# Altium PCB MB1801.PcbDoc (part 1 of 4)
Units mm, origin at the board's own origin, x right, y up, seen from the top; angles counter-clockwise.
Board outline 70.1 x 57.1 mm, 4 copper layers (Top Layer, Signal Layer 1, Signal Layer 2, Bottom Layer), stack 1.614 mm thick; 219 components, 166 nets, 1002 pads, 473 vias.
Unrouted connection lines stored in the file: 2.
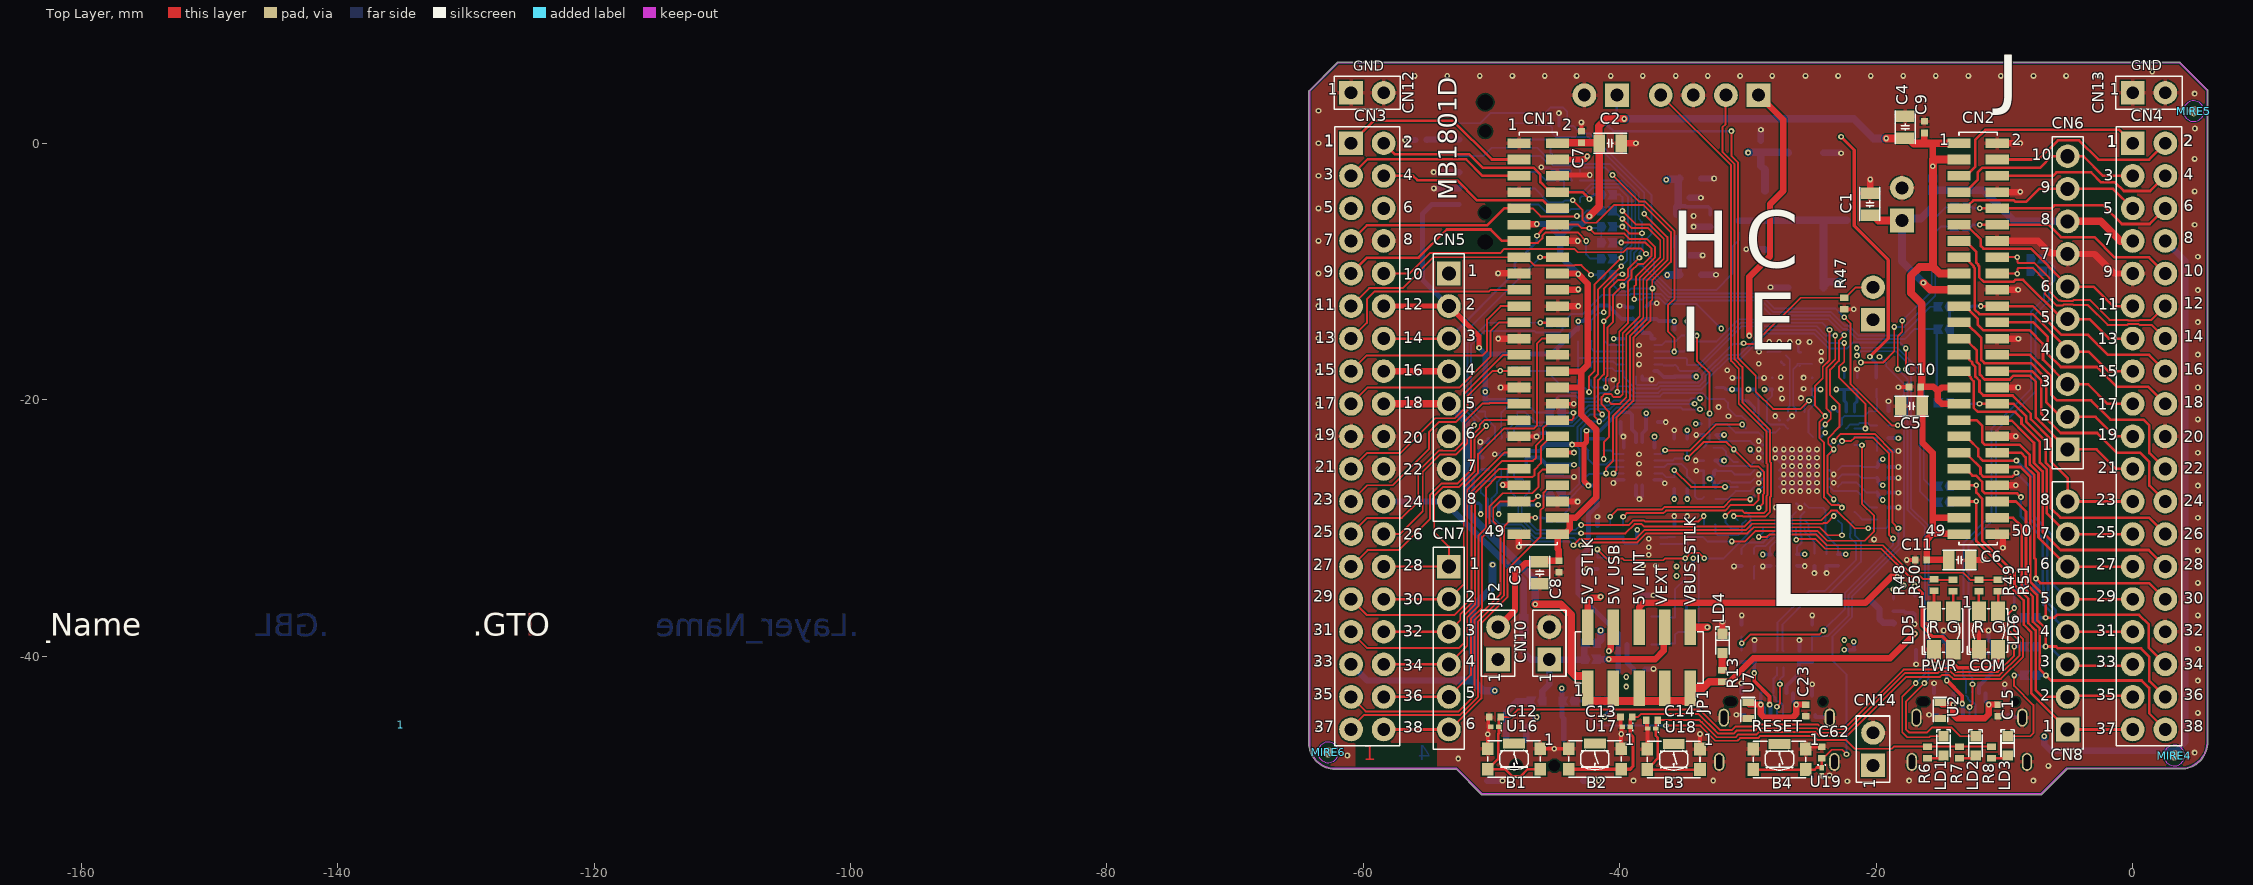
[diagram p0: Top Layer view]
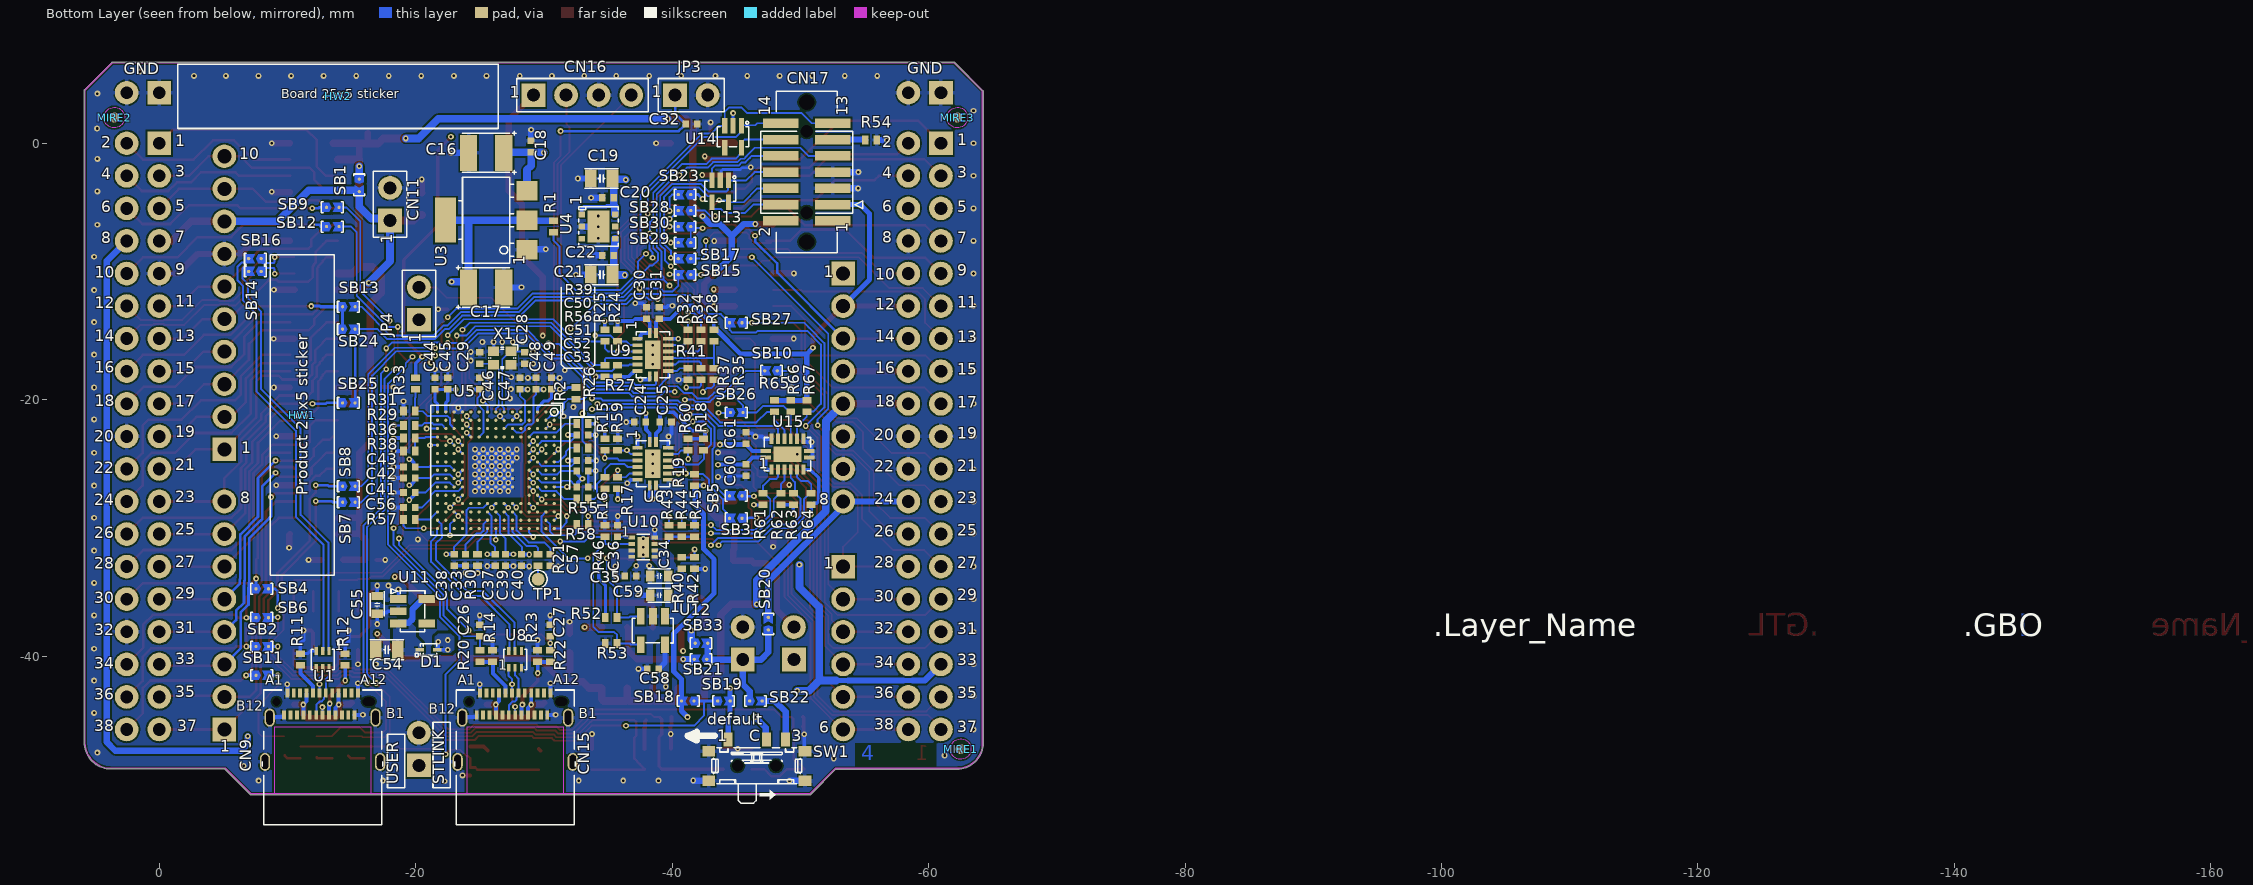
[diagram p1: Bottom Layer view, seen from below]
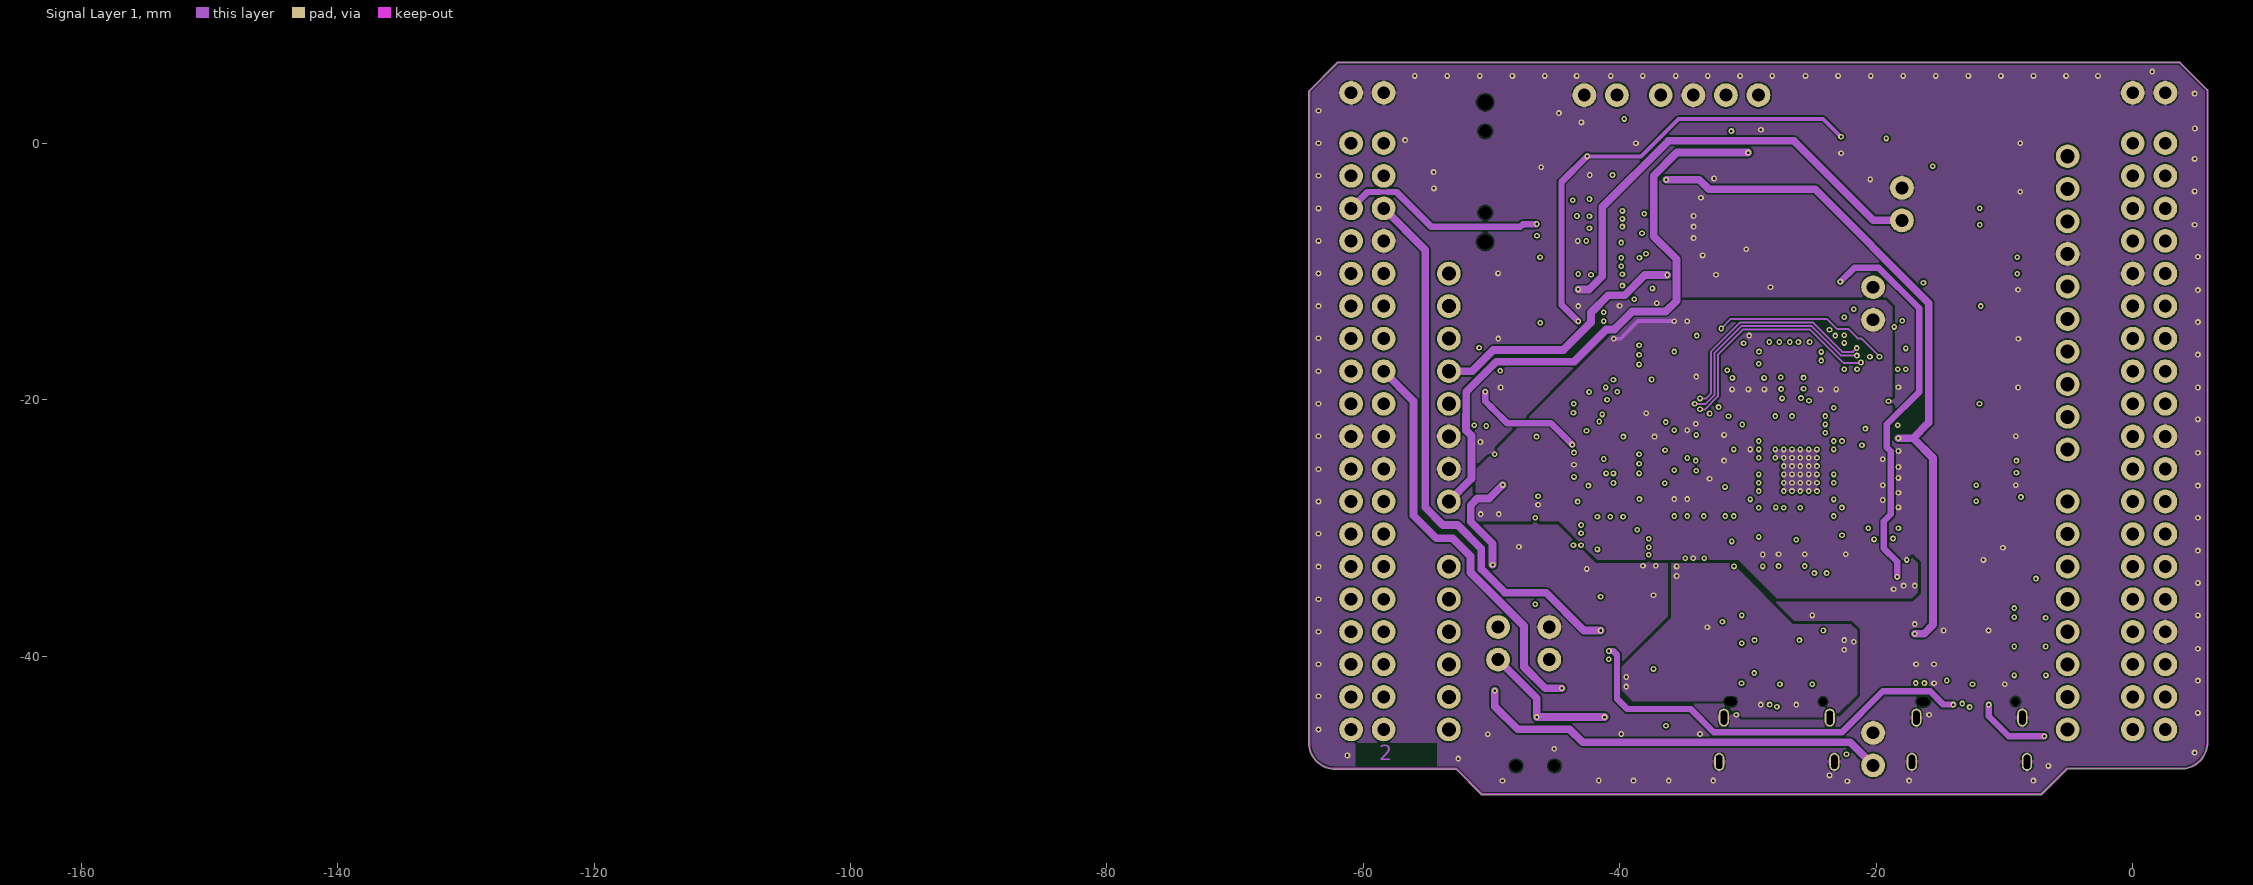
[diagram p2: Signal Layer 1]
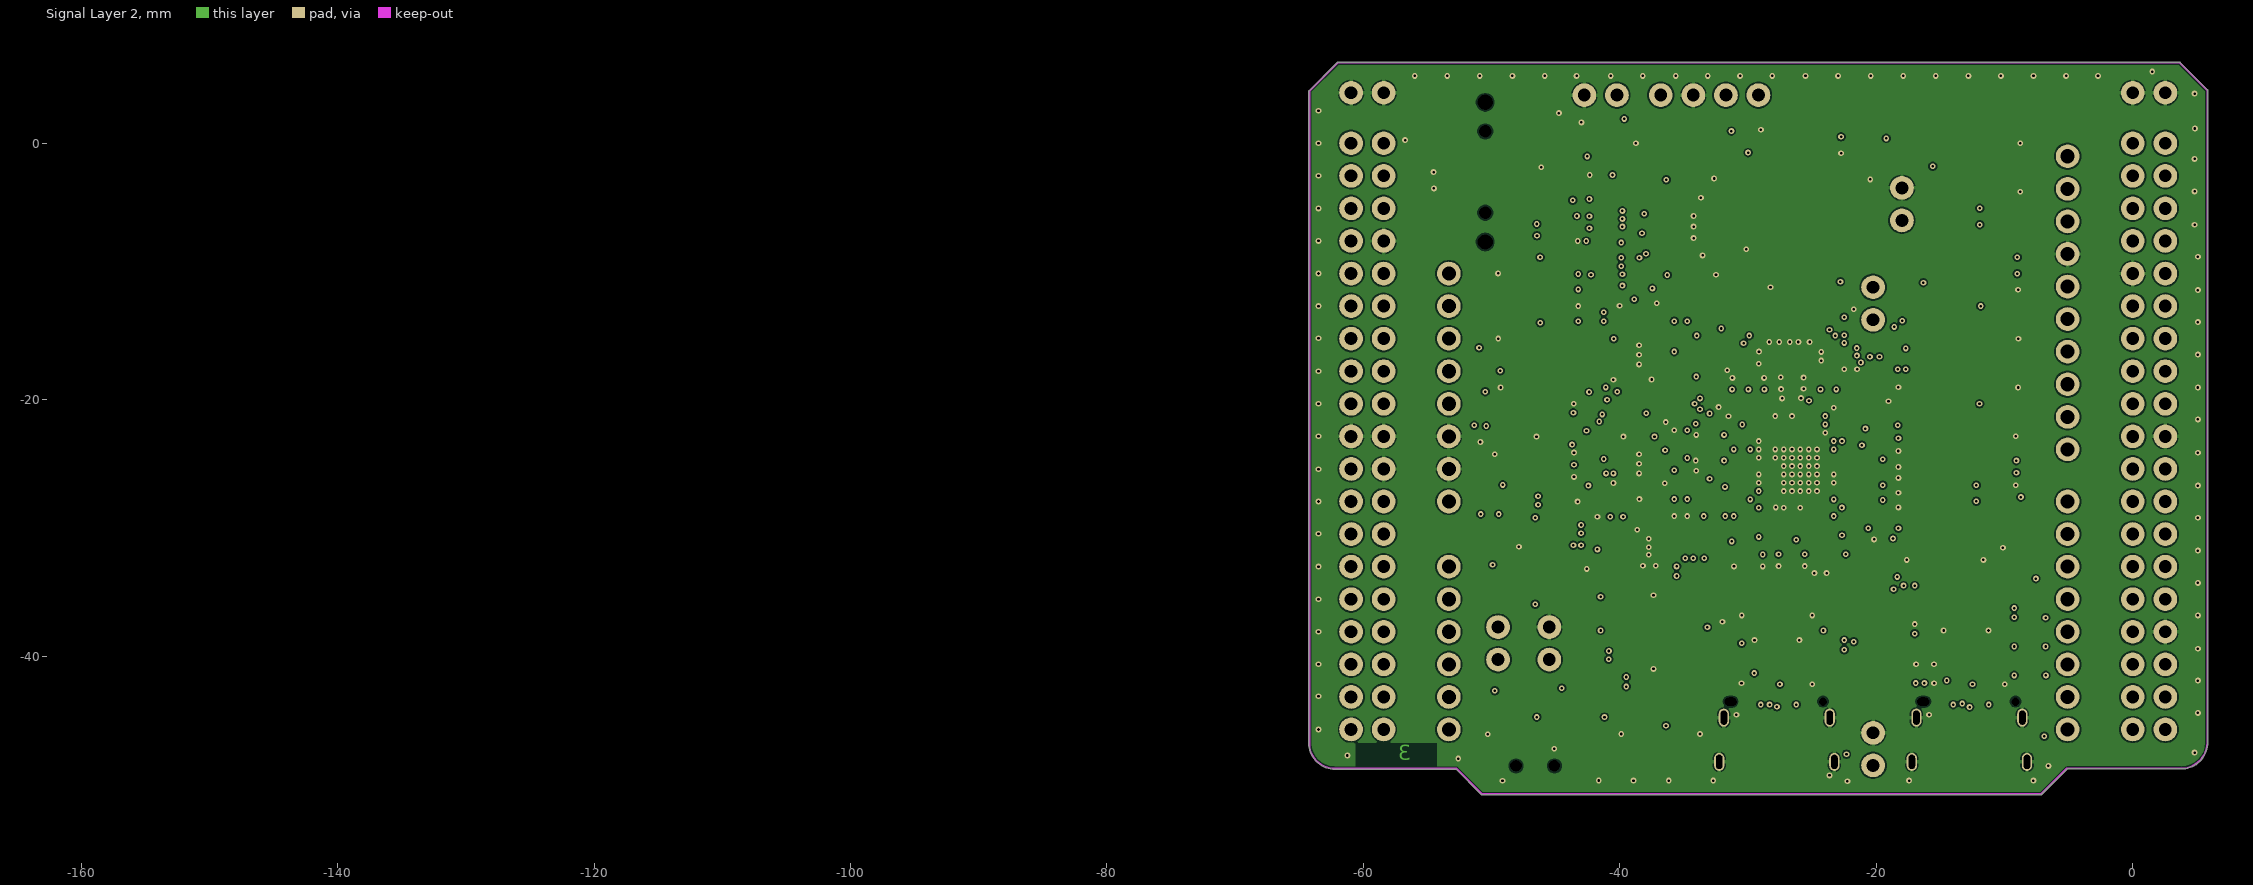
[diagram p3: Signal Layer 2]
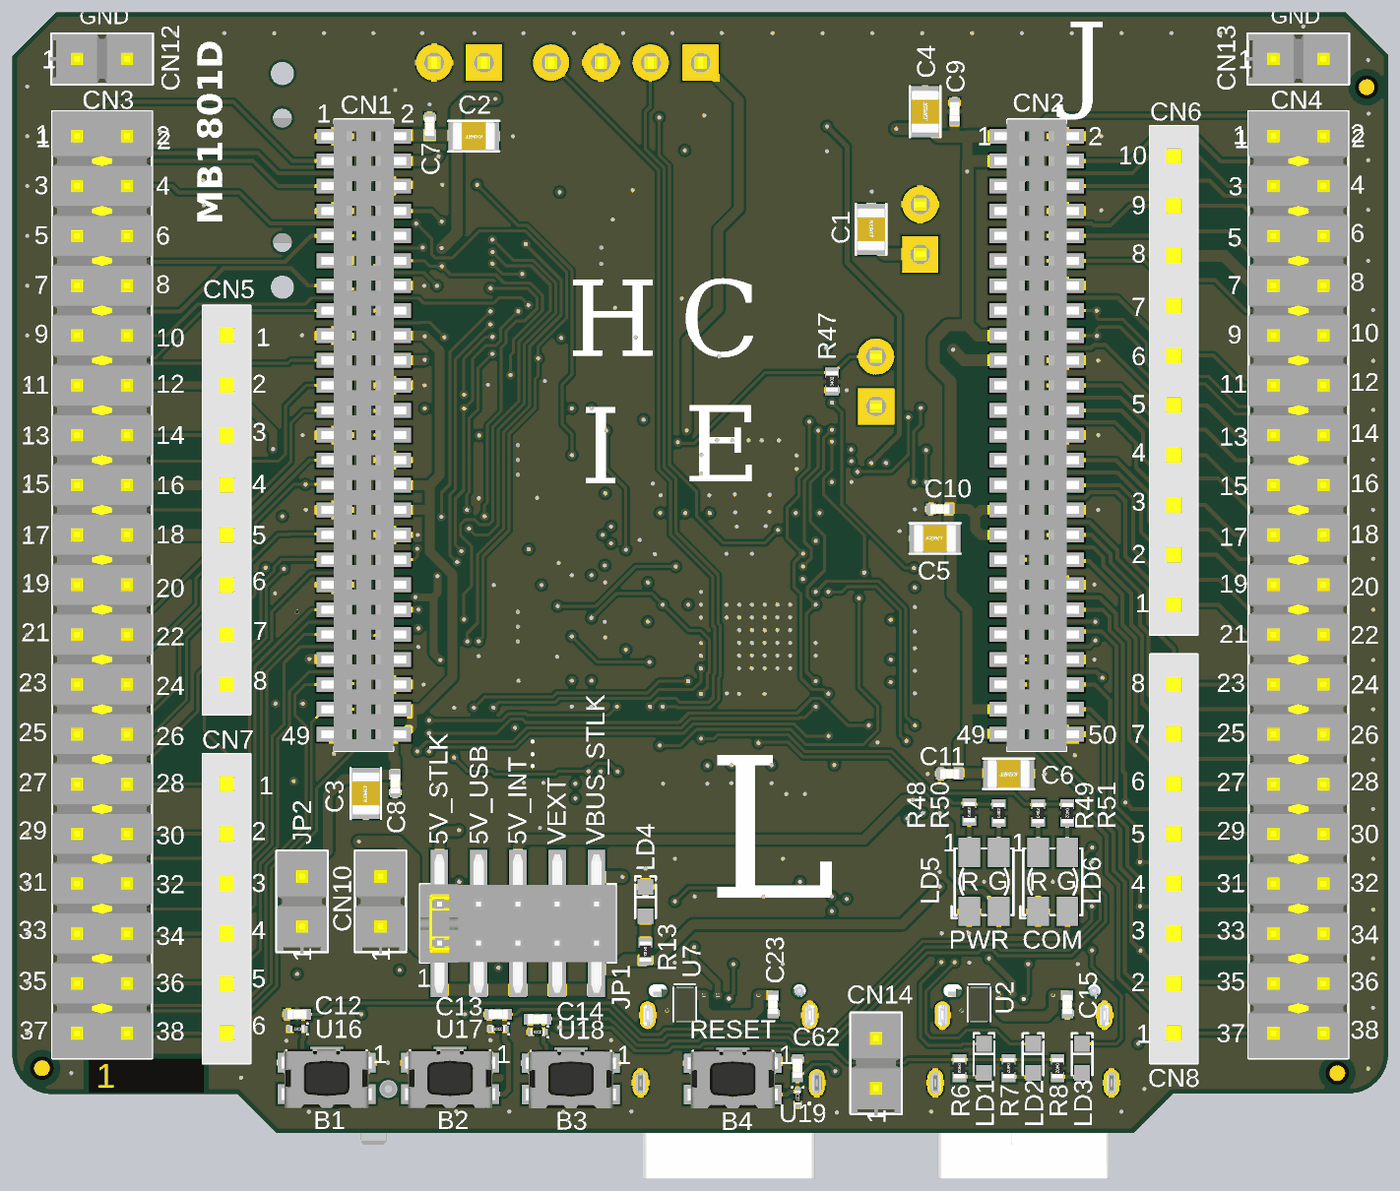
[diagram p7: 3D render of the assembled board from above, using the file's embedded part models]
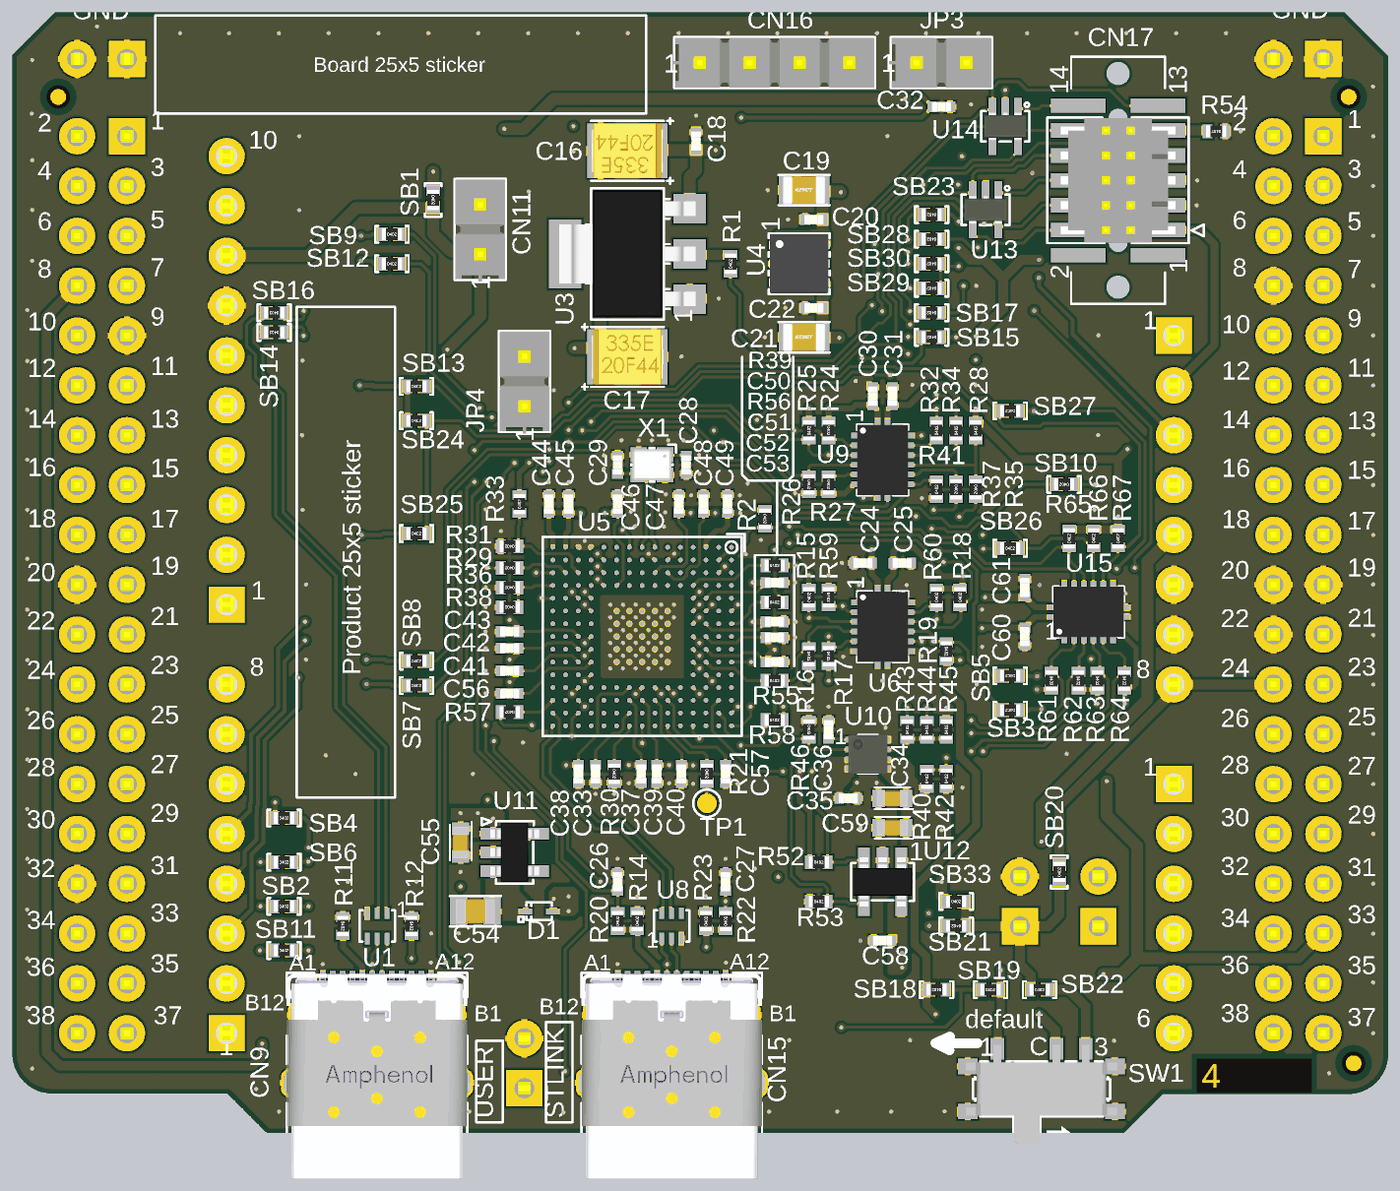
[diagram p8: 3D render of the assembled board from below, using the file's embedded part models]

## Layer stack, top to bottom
Top Solder: solder mask 0.015, Solder Resist, Dk 3.5
Top Layer: signal copper 0.042
Dielectric 1: prepreg 0.106, PP-IT-180A, Dk 4.2
Signal Layer 1: signal copper 0.035
Dielectric 2: dielectric 1.248, FR-4, Dk 4.2
Signal Layer 2: signal copper 0.035
Dielectric 3: prepreg 0.106, PP-IT-180A, Dk 4.2
Bottom Layer: signal copper 0.042
Bottom Solder: solder mask 0.015, Solder Resist, Dk 3.5

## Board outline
-62.21,-48.818 ccw(c-62.21,-48.768) -62.183,-48.81 -52.79,-48.81 -50.822,-50.778 ccw(c-50.786,-50.743) -50.786,-50.793 -7.131,-50.793 ccw(c-7.131,-50.743) -7.095,-50.778 -5.11,-48.793 3.79,-48.793 ccw(c3.79,-46.743) 5.84,-46.743 ccw(c5.79,-46.743) 5.84,-46.742 5.84,2.211 5.84,4.125 ccw(c5.79,4.125) 5.825,4.161 5.826,4.16 3.693,6.293 3.694,6.292 ccw(c3.658,6.257) 3.658,6.307 -62.001,6.307 ccw(c-62.001,6.257) -62.037,6.292 -62.037,6.293 -64.246,4.084 -64.245,4.084 ccw(c-64.21,4.048) -64.26,4.048 -64.26,-46.768 ccw(c-64.21,-46.768) -64.26,-46.769 cw(c-62.21,-46.768) -64.26,-46.768 -64.26,-46.769 ccw(c-62.21,-46.768)

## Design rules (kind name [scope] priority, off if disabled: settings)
Clearance [All] p1: gap=0.125 ignorepadtopadclearanceinfootprint=FALSE except(0.109: SMDPad-Via; 0.12: Arc-SMDPad Track-SMDPad; 0.223: Fill-Fill Fill-Poly Fill-Region Poly-Poly Poly-Region Region-Region)
ComponentClearance [All] p1: gap=0.2 collisioncheckmode=3 verticalgap=0.2 showdistances=FALSE
DiffPairsRouting [All] p1: maxlimit=0.226 minlimit=0.125 mostfreqgap=0.226 toplayer_minwidth=0.155 toplayer_maxwidth=0.155 toplayer_prefwidth=0.155 midlayer1_mingap=0.127 midlayer1_maxgap=0.127 midlayer1_prefgap=0.127 midlayer1_minwidth=0.083 midlayer1_maxwidth=0.083 midlayer1_prefwidth=0.083 midlayer2_mingap=0.127 midlayer2_maxgap=0.127 midlayer2_prefgap=0.127 midlayer2_minwidth=0.083 midlayer2_maxwidth=0.083 midlayer2_prefwidth=0.083 bottomlayer_mingap=0.15 bottomlayer_minwidth=0.155 bottomlayer_maxwidth=0.155 bottomlayer_prefwidth=0.155 impedanceprofiledriven=TRUE impedanceprofileid={D0817542-EEAA-4EE1-A293-D078BA0B5E8B} impedanceprofilevalue=90.000000 maxuncoupledlength=1.5
HoleSize [All] p1: absolutevalues=TRUE maxlimit=10 minlimit=0.025 maxpercent=80.000 minpercent=20.000
MatchedLengths "Schematic Matched Net Lengths_3" [InNet('USB_C_P')] p1: tolerance=2 checknetsindiffpair=TRUE checkdiffpairvsdiffpair=FALSE checkxsignals=FALSE checkothers=FALSE
MatchedLengths "Schematic Matched Net Lengths_2" [InNet('USB_C_N')] p2: tolerance=2 checknetsindiffpair=TRUE checkdiffpairvsdiffpair=FALSE checkxsignals=FALSE checkothers=FALSE
MatchedLengths "Schematic Matched Net Lengths_1" [InNet('USB_N')] p3: tolerance=2 checknetsindiffpair=TRUE checkdiffpairvsdiffpair=FALSE checkxsignals=FALSE checkothers=FALSE
MatchedLengths "Schematic Matched Net Lengths" [InNet('USB_P')] p4: tolerance=2 checknetsindiffpair=TRUE checkdiffpairvsdiffpair=FALSE checkxsignals=FALSE checkothers=FALSE
MaxMinImpedance "Schematic Impedance Constraint_4" [InNet('USB_FS_P')] p1: minimum=85.00 maximum=95.00
MaxMinImpedance "Schematic Impedance Constraint_3" [InNet('USB_FS_N')] p2: minimum=85.00 maximum=95.00
MaxMinImpedance "Schematic Impedance Constraint_2" [InNet('STLK_USB_P')] p3: minimum=85.00 maximum=95.00
MaxMinImpedance "Schematic Impedance Constraint_1" [InNet('STLK_USB_N')] p4: minimum=85.00 maximum=95.00
MaxMinImpedance "Schematic Impedance Constraint_8" [InNet('USB_C_N')] p5: minimum=85.00 maximum=95.00
MaxMinImpedance "Schematic Impedance Constraint_7" [InNet('USB_N')] p6: minimum=85.00 maximum=95.00
MaxMinImpedance "Schematic Impedance Constraint_6" [InNet('USB_C_P')] p7: minimum=85.00 maximum=95.00
MaxMinImpedance "Schematic Impedance Constraint" [InNet('USB_P')] p8: minimum=85.00 maximum=95.00
MinimumSolderMaskSliver [All] p1: minsoldermaskwidth=0.1
PlaneConnect [All] p1: planeconnectstyle=Direct reliefexpansion=0.508 reliefentries=4 reliefconductorwidth=0.21 reliefairgap=0.21
PolygonConnect PolygonConnect_via [IsVia] p1: connectstyle=Direct reliefconductorwidth=0.254 reliefentries=4 polygonreliefangle="90 Angle" airgapwidth=0.254
PolygonConnect [All] p2: connectstyle=Relief reliefconductorwidth=0.3 reliefentries=4 polygonreliefangle="90 Angle" airgapwidth=0.1
RoutingVias [All] p1: holewidth=0.2 width=0.45 viastyle="Through Hole" minholewidth=0.2 minwidth=0.45 maxholewidth=0.2 maxwidth=0.45
SilkToSilkClearance [All] p1: silktosilkclearance=0.2
SilkToSolderMaskClearance [IsPad] p1: minsilkscreentomaskgap=0.2 clearancetoexposedcopper=TRUE
SolderMaskExpansion [All] p1: expansion=0.102 istentingtop=FALSE
Width [All] p1: maxlimit=0.8 minlimit=0.15 preferedwidth=0.15 minimp=50.000000 maximp=50.000000 favimp=50.000000
23 further rules are at their usual default settings.

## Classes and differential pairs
component class U_External_Debug_Interface: CN17 LD5 LD6 R48 R49 R50 R51 R54 U13 U14
component class Project_Overview: HW1 HW2
component class U_STlink-V3EC: C23 C24 C25 C26 C27 C28 C29 C30 C31 C32 C33 C34 C35 C36 C37 C38 C39 C40 C41 C42 C43 C44 C45 C46 C47 C48 C49 C50 C51 C52 C53 C54 C55 C56 C57 C58 C59 C60 C61 CN15 CN16 D1 JP3 JP4 R2 R14 R15 R16 R17 R18 R19 R20 R21 R22 R23 R24 R25 R26 R27 R28 R29 R30 R31 R32 R33 R34 R35 R36 R37 R38 R39 R40 R41 R42 R43 R44 R45 R46 R47 R52 R53 R55 R56 R57 R58 R59 R60 R61 R62 R63 R64 R65 R66 R67 TP1 U5 U6 U7 U8 U9 U10 U11 U12 U15 X1
component class "Power Management": C16 C17 C18 C19 C20 C21 C22 CN10 CN12 CN13 JP1 JP2 LD4 R13 SB20 SB21 SB22 SB33 SW1 U3 U4
component class "LEDs & Push Buttons & USB-C Connector": B1 B2 B3 B4 C12 C13 C14 C15 C62 CN9 LD1 LD2 LD3 R6 R7 R8 R11 R12 SB18 SB19 U1 U2 U16 U17 U18 U19
component class "Extension Connectors": C1 C2 C3 C4 C5 C6 C7 C8 C9 C10 C11 CN1 CN2 CN3 CN4 CN5 CN6 CN7 CN8 CN11 CN14 R1 SB1 SB2 SB3 SB4 SB5 SB6 SB7 SB8 SB9 SB10 SB11 SB12 SB13 SB14 SB15 SB16 SB17 SB23 SB24 SB25 SB26 SB27 SB28 SB29 SB30
differential pair USB_FS: +USB_FS_P -USB_FS_N
differential pair STLK_USB: +STLK_USB_P -STLK_USB_N
differential pair USB: +USB_P -USB_N
differential pair USB_C: +USB_C_P -USB_C_N

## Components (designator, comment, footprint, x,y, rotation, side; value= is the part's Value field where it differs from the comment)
1 "Comment" Sheetbox_2L2S -180.167,-50.702 r0 top
B1 "SW-PUSH-CMS_KMR2_BLACK" SWI_C&K_Y78B23110FP__ITT_KMR231GLFS -48.25,-48.022 r0 top value=KMR231GLFS
B2 "SW-PUSH-CMS_KMR2_BLACK" SWI_C&K_Y78B23110FP__ITT_KMR231GLFS -41.95,-48.022 r0 top value=KMR231GLFS
B3 "SW-PUSH-CMS_KMR2_BLACK" SWI_C&K_Y78B23110FP__ITT_KMR231GLFS -35.8,-48.05 r0 top value=KMR231GLFS
B4 "SW-PUSH-CMS_KMR2_BLACK" SWI_C&K_Y78B23110FP__ITT_KMR231GLFS -27.55,-48.05 r0 top value=KMR231GLFS
C1 "Capacitor" C0805_H0P85 -20.5,-4.75 r270 top value=1uF
C2 "Capacitor" C0805_H0P85 -40.75,0 r180 top value=1uF
C3 "Capacitor" C0805_H0P85 -46.25,-33.5 r90 top value=1uF
C4 "Capacitor" C0805_H0P85 -17.75,1.25 r270 top value=1uF
C5 "Capacitor" C0805_H0P85 -17.25,-20.5 r0 top value=1uF
C6 "Capacitor" C0805_H0P85 -13.5,-32.5 r180 top value=1uF
C7 "Capacitor" C0402 -43,0.5 r270 top value=100nF
C8 "Capacitor" C0402 -44.75,-33 r90 top value=100nF
C9 "Capacitor" C0402 -16.25,1.25 r270 top value=100nF
C10 "Capacitor" C0402 -17,-19 r0 top value=100nF
C11 "Capacitor" C0402 -16.5,-32.5 r0 top value=100nF
C12 "Capacitor" C0402 -49.75,-44.75 r0 top value=10nF
C13 "Capacitor" C0402 -39.5,-44.75 r0 top value=10nF
C14 "Capacitor" C0402 -37.5,-45 r0 top value=10nF
C15 "Capacitor" C0402 -10.5,-44.25 r90 top value=100pF
C16 "Cap_POL_TANA" CPOL_TAJ-B_1210_H210 -25.5,-0.75 r0 bottom value=10uF
C17 "Cap_POL_TANA" CPOL_TAJ-B_1210_H210 -25.5,-11.25 r180 bottom value=10uF
C18 "Capacitor" C0402 -29,-0.25 r270 bottom value=100nF
C19 "Capacitor" C0805_H0P85 -34.5,-2.75 r180 bottom value=1uF
C20 "Capacitor" C0402 -35,-4.25 r180 bottom value=100nF
C21 "Capacitor" C0805_H0P85 -34.5,-10.25 r180 bottom value=1uF
C22 "Capacitor" C0402 -35,-8.75 r180 bottom value=100nF
C23 "Capacitor" C0402 -25.5,-44.25 r270 top value=100pF
C24 "Capacitor" C0402 -37.5,-21.75 r180 bottom value=100nF
C25 "Capacitor" C0402 -39.5,-21.75 r180 bottom value=100nF
C26 "Capacitor" C0402 -25,-38 r90 bottom value=10nF
C27 "Capacitor" C0402 -30.5,-38 r90 bottom value=10nF
C28 "Capacitor" C0402 -28.5,-16.75 r90 bottom value=2.7pF
C29 "Capacitor" C0402 -25,-16.75 r90 bottom value=2.7pF
C30 "Capacitor" C0402 -38,-13.25 r270 bottom value=100nF
C31 "Capacitor" C0402 -39,-13.25 r90 bottom value=100nF
C32 "Capacitor" C0402 -41.5,1.5 r0 bottom value=100nF
C33 "Capacitor" C0402 -23.875,-32.5 r90 bottom value=2.2uF
C34 "Capacitor" C0603 -39,-33.75 r180 bottom value=10uF
C35 "Capacitor" C0402 -36.75,-33.75 r0 bottom value=100nF
C36 "Capacitor" C0402 -35.75,-30.25 r270 bottom value=10nF
C37 "Capacitor" C0402 -26.2,-32.5 r270 bottom value=100nF
C38 "Capacitor" C0402 -23,-32.5 r270 bottom value=100nF
C39 "Capacitor" C0402 -27,-32.5 r270 bottom value=100nF
C40 "Capacitor" C0402 -28.25,-32.5 r270 bottom value=100nF
C41 "Capacitor" C0402 -19.5,-27.25 r0 bottom value=100nF
C42 "Capacitor" C0402 -19.5,-26.1 r0 bottom value=100nF
C43 "Capacitor" C0402 -19.5,-25.25 r0 bottom value=100nF
C44 "Capacitor" C0402 -21.5,-18.75 r90 bottom value=100nF
C45 "Capacitor" C0402 -22.5,-18.75 r90 bottom value=100nF
C46 "Capacitor" C0402 -25,-18.75 r90 bottom value=100nF
C47 "Capacitor" C0402 -28.125,-18.75 r90 bottom value=100nF
C48 "Capacitor" C0402 -29.375,-18.75 r90 bottom value=100nF
C49 "Capacitor" C0402 -30.6,-18.75 r90 bottom value=100nF
C50 "Capacitor" C0402 -33,-22.75 r180 bottom value=100nF
C51 "Capacitor" C0402 -33,-24.75 r180 bottom value=100nF
C52 "Capacitor" C0402 -33,-25.55 r180 bottom value=100nF
C53 "Capacitor" C0402 -33,-26.8 r180 bottom value=100nF
C54 "Capacitor" C0805 -17.75,-39.5 r180 bottom value=2.2uF
C55 "Capacitor" C0603 -17,-36 r90 bottom value=10uF
C56 "Capacitor" C0402 -19.5,-28.4 r180 bottom value=2.2uF
C57 "Capacitor" C0402 -30.5,-32.5 r90 bottom value=2.2uF
C58 "Capacitor" C0402 -38.5,-41 r180 bottom value=100nF
C59 "Capacitor" C0603 -39,-35.25 r180 bottom value=10uF
C60 "Capacitor" C0402 -45.75,-25.5 r90 bottom value=100nF
C61 "Capacitor" C0402 -45.75,-23 r90 bottom value=100nF
C62 "Capacitor" C0402 -24.25,-47.5 r90 top value=100nF
CN1 "CLP-125-02-F-D" CON_SAMTEC_CLP-125-02-F-D -46.355,-15.24 r0 top locked value="Socket 25x2"
CN2 "CLP-125-02-F-D" CON_SAMTEC_CLP-125-02-F-D -12.065,-15.24 r0 top locked value="Socket 25x2"
CN3 "Header 19x2" CON_SAMTEC_TSW-119-09-X-D -59.69,-22.86 r270 top locked
CN4 "Header 19x2" CON_SAMTEC_TSW-119-09-X-D 1.27,-22.86 r270 top locked
CN5 "Socket 8x1" CON_SAMTEC_SSW-108-01-X-S -53.34,-19.05 r270 top locked
CN6 "Socket 10x1" CON_SAMTEC_SSW-110-01-X-S -5.08,-12.446 r90 top locked
CN7 "Socket 6x1" CON_SAMTEC_SSW-106-01-X-S -53.34,-39.37 r270 top locked
CN8 "Socket 8x1" CON_SAMTEC_SSW-108-01-X-S -5.08,-36.83 r90 top locked
CN9 "USB_TYPE_C_Receptacle" CON_USB-TYPEC_AMPHENOL_12401826E412A -12.74,-43.55 r180 bottom value=USB_C_12401826E412A
CN10 "Header 2x1" CON_SAMTEC_TSW-102-07-G-S -45.5,-39 r90 top
CN11 "Header 2x1" CON_SAMTEC_TSW-102-07-G-S -18,-4.75 r90 bottom
CN12 "Header 2x1" CON_SAMTEC_TSW-102-07-G-S -59.69,3.937 r0 top
CN13 "Header 2x1" CON_SAMTEC_TSW-102-07-G-S 1.27,3.937 r0 top locked
CN14 "Header 2x1" CON_SAMTEC_TSW-102-07-G-S -20.25,-47.25 r90 top
CN15 "USB_TYPE_C_Receptacle" CON_USB-TYPEC_AMPHENOL_12401826E412A -27.76,-43.55 r180 bottom value=USB_C_12401826E412A
CN16 "Header 4x1" CON_SAMTEC_TSW-104-07-G-S -33,3.75 r180 bottom
CN17 "Header 7x2" CON_STDC14_Receiver_MEDIUM_WITH_MIPI10_3D -50.5,-2.25 r90 bottom value="Header 5x2"
D1 "SCHOTTKY_1A_2K" DIO_SOD523_1A_2K -21,-39.5 r0 bottom value=BAT54KFILM
HW1 "STICKER_PRODUCT" STICKER_PRODUCT_25X5 -11.15,-21.2 r270 bottom value="Sticker product"
HW2 "STICKER_BOARD" STICKER_BOARD_25X5 -13.95,3.65 r180 bottom value="Sticker board"
JP1 "Jumper 5 Positions" CON_SAMTEC_TMM-105-06-T-D-SM -38.5,-40.125 r0 top value=TMM-105-06-T-D-SM
JP2 "Jumper_Header 2x1 Fitted" CON_SAMTEC_TSW-102-07-G-S -49.5,-39 r90 top value="Header 2x1"
JP3 "Jumper_Header 2x1" CON_SAMTEC_TSW-102-07-G-S -41.5,3.75 r180 bottom
JP4 "Jumper_Header 2x1" CON_SAMTEC_TSW-102-07-G-S -20.25,-12.5 r90 bottom
LD1 "LED_blue" LED_0603_VISHAY_VLMB1300-GS08_BLUE_1A2K_H0P8 -14.75,-47 r90 top value=BLUE
LD2 "LED_green" LED_0603_VISHAY_VLMTG1300-GS08_GREEN_1A2K_H0P8 -12.25,-47 r90 top value="TRUE GREEN"
LD3 "LED_red" LED_0603_VISHAY_VLMS1300-GS08_RED_1A2K_H0P8 -9.75,-47 r90 top value=RED
LD4 "LED_green" LED_0603_VISHAY_VLMTG1300-GS08_GREEN_1A2K_H0P8 -32,-39 r90 top value="TRUE GREEN"
LD5 "LED_BICOLOR" LED_BI-GR_WE-150141SV73110 -14.75,-38 r0 top value="Green / Red"
LD6 "LED_BICOLOR" LED_BI-GR_WE-150141SV73110 -11.25,-38 r0 top value="Green / Red"
MIRE1 "Comment" MIRE_PLACE_SMD_0P8MM -62.5,-47.25 r0 bottom
MIRE2 "Comment" MIRE_PLACE_SMD_0P8MM 3.5,2 r0 bottom
MIRE3 "Comment" MIRE_PLACE_SMD_0P8MM -62.25,2 r0 bottom
MIRE4 "Comment" MIRE_PLACE_SMD_0P8MM 3.25,-47.75 r0 top
MIRE5 "Comment" MIRE_PLACE_SMD_0P8MM 4.75,2.5 r0 top
MIRE6 "Comment" MIRE_PLACE_SMD_0P8MM -62.75,-47.5 r0 top
R1 "Resistor" R0402 -30.75,-6.5 r90 bottom value=1K
R2 "Resistor" R0402 -32.5,-19.5 r270 bottom value=100K
R6 "Resistor" R0402 -16,-47.5 r270 top value=680R
R7 "Resistor" R0402 -13.5,-47.5 r270 top value=680R
R8 "Resistor" R0402 -11,-47.5 r270 top value=680R
R11 "Resistor" R0402 -11,-40.25 r270 bottom value=5K1
R12 "Resistor" R0402 -14.5,-40.25 r270 bottom value=5K1
R13 "Resistor" R0402 -32,-41.55 r270 top value=1K5
R14 "Resistor" R0402 -26,-40 r90 bottom value=5K1
R15 "Resistor" R0402 -34.75,-23.5 r90 bottom value=100K
R16 "Resistor" R0402 -34.75,-26.5 r270 bottom value=100K
R17 "Resistor" R0402 -35.75,-26.5 r270 bottom value=100K
R18 "Resistor" R0402 -42.45,-23.5 r90 bottom value=100K
R19 "Resistor" R0402 -41.75,-26.25 r270 bottom value=100K
R20 "Resistor" R0402 -25,-40 r90 bottom value=100K
R21 "Resistor" R0402 -29.55,-32.5 r270 bottom value=0R
R22 "Resistor" R0402 -30.5,-40 r90 bottom value=100K
R23 "Resistor" R0402 -29.5,-40 r90 bottom value=5K1
R24 "Resistor" R0402 -35.75,-15 r270 bottom value=100K
R25 "Resistor" R0402 -34.75,-15 r90 bottom value=100K
R26 "Resistor" R0402 -34.75,-17.75 r270 bottom value=100K
R27 "Resistor" R0402 -35.75,-17.75 r270 bottom value=100K
R28 "Resistor" R0402 -43.25,-15 r90 bottom value=100K
R29 "Resistor" R0402 -19.5,-22 r0 bottom value=0R
R30 "Resistor" R0402 -24.825,-32.5 r270 bottom value=3K
R31 "Resistor" R0402 -19.5,-20.9 r0 bottom value=10K
R32 "Resistor" R0402 -41.25,-15 r90 bottom value=47R
R33 "Resistor" R0402 -20,-18.75 r90 bottom value=10K
R34 "Resistor" R0402 -42.25,-15 r90 bottom value=47R
R35 "Resistor" R0402 -43.25,-18 r270 bottom value=47R
R36 "Resistor" R0402 -19.5,-23 r0 bottom value=5K1
R37 "Resistor" R0402 -42.25,-18 r270 bottom value=47R
R38 "Resistor" R0402 -19.5,-24 r0 bottom value=10K
R39 "Resistor" R0402 -33,-21.875 r180 bottom value=10K
R40 "Resistor" R0402 -40.75,-32.75 r90 bottom value=3K
R41 "Resistor" R0402 -41.25,-18 r90 bottom value=100K
R42 "Resistor" R0402 -41.75,-32.75 r90 bottom value=5K1
R43 "Resistor" R0402 -39.75,-30.25 r90 bottom value=1K8
R44 "Resistor" R0402 -40.75,-30.25 r90 bottom value=1K3
R45 "Resistor" R0402 -41.75,-30.25 r90 bottom value=3K9
R46 "Resistor" R0402 -34.75,-30.25 r270 bottom value=100K
R47 "Resistor" R0402 -22.5,-12.5 r90 top value=100K
R48 "Resistor" R0402 -15.5,-34.45 r90 top value=1K
R49 "Resistor" R0402 -12,-34.5 r90 top value=1K
R50 "Resistor" R0402 -14,-34.5 r90 top value=330R
R51 "Resistor" R0402 -10.5,-34.5 r270 top value=330R
R52 "Resistor" R0402 -35.25,-37 r180 bottom value=100K
R53 "Resistor" R0402 -35.25,-39 r180 bottom value=100K
R54 "Resistor" R0402 -55.5,0.25 r0 bottom value=100R
R55 "Resistor" R0402 -33,-27.75 r180 bottom value=0R
R56 "Resistor" R0402 -33,-23.75 r180 bottom value=33R
R57 "Resistor" R0402 -19.5,-29.35 r0 bottom value=0R
R58 "Resistor" R0402 -33,-29.75 r180 bottom value=33R
R59 "Resistor" R0402 -35.75,-23.5 r270 bottom value=100K
R60 "Resistor" R0402 -41.25,-23.5 r90 bottom value=100K
R61 "Resistor" R0402 -47.1,-27.75 r270 bottom value=100K
R62 "Resistor" R0402 -48.475,-27.75 r270 bottom value=100K
R63 "Resistor" R0402 -49.45,-27.75 r270 bottom value=100K
R64 "Resistor" R0402 -50.825,-27.75 r270 bottom value=100K
R65 "Resistor" R0402 -48,-20.5 r90 bottom value=100K
R66 "Resistor" R0402 -49.25,-20.5 r90 bottom value=100K
R67 "Resistor" R0402 -50.5,-20.5 r90 bottom value=100K
SB1 "SB_ON" SOLDER-BRIDGE_R0402-0R -15.6,-3.25 r270 bottom
SB2 "SB_ON" SOLDER-BRIDGE_R0402-0R -8,-39.25 r180 bottom
SB3 "SB_ON" SOLDER-BRIDGE_R0402-0R -45,-29.25 r0 bottom
SB4 "SB_ON" SOLDER-BRIDGE_R0402-0R -8,-34.75 r180 bottom
SB5 "SB_ON" SOLDER-BRIDGE_R0402-0R -45,-27.5 r0 bottom
SB6 "SB_ON" SOLDER-BRIDGE_R0402-0R -8,-37 r180 bottom
SB7 "SB_ON" SOLDER-BRIDGE_R0402-0R -14.75,-28 r180 bottom
SB8 "SB_ON" SOLDER-BRIDGE_R0402-0R -14.75,-26.75 r180 bottom
SB9 "SB_ON" SOLDER-BRIDGE_R0402-0R -13.5,-5 r180 bottom
SB10 "SB_ON" SOLDER-BRIDGE_R0402-0R -47.75,-17.75 r0 bottom
SB11 "SB_ON" SOLDER-BRIDGE_R0402-0R -8,-41.5 r180 bottom
SB12 "SB_ON" SOLDER-BRIDGE_R0402-0R -13.5,-6.5 r180 bottom
SB13 "SB_ON" SOLDER-BRIDGE_R0402-0R -14.75,-12.75 r180 bottom
SB14 "SB_ON" SOLDER-BRIDGE_R0402-0R -7.5,-10 r0 bottom
SB15 "SB_ON" SOLDER-BRIDGE_R0402-0R -41,-10.25 r0 bottom
SB16 "SB_ON" SOLDER-BRIDGE_R0402-0R -7.5,-9 r0 bottom
SB17 "SB_ON" SOLDER-BRIDGE_R0402-0R -41,-9 r0 bottom
SB18 "SB_ON" SOLDER-BRIDGE_R0402-0R -41.25,-43.5 r0 bottom
SB19 "SB_ON" SOLDER-BRIDGE_R0402-0R -44,-43.5 r180 bottom
SB20 "SB_ON" SOLDER-BRIDGE_R0402-0R -47.5,-37.5 r90 bottom
SB21 "SB_ON" SOLDER-BRIDGE_R0402-0R -42.25,-40.25 r0 bottom
SB22 "SB_ON" SOLDER-BRIDGE_R0402-0R -46.5,-43.5 r180 bottom
SB23 "SB_ON" SOLDER-BRIDGE_R0402-0R -41,-4 r0 bottom
SB24 "SB_ON" SOLDER-BRIDGE_R0402-0R -14.75,-14.5 r180 bottom
SB25 "SB_ON" SOLDER-BRIDGE_R0402-0R -14.75,-20.25 r180 bottom
SB26 "SB_ON" SOLDER-BRIDGE_R0402-0R -45,-21 r180 bottom
SB27 "SB_ON" SOLDER-BRIDGE_R0402-0R -45,-14 r0 bottom
SB28 "SB_ON" SOLDER-BRIDGE_R0402-0R -41,-5.25 r0 bottom
SB29 "SB_ON" SOLDER-BRIDGE_R0402-0R -41,-7.75 r0 bottom
SB30 "SB_ON" SOLDER-BRIDGE_R0402-0R -41,-6.5 r0 bottom
SB33 "SB_ON" SOLDER-BRIDGE_R0402-0R -42.25,-39 r180 bottom
SW1 "SW_MECA" SWI_SPDT-RA_TE-CONNECTIVITY_MLL1200S_1P2T -46.6,-48.559 r180 bottom locked value=Switch-Slider_3x1_PCM12SMTR
TP1 "Test Point" TP_SMD_1MM -29.55,-34 r180 bottom
U1 "ECMF02-2AMX6" ESD_QFN-6L_1P7X1P5_P050 -12.75,-40.25 r0 bottom
U2 "ESD-TRANSIL" ESD_QFN1610_2N_1K_2A -15,-44.25 r270 top value=ESDA25P35-1U1M
U3 "LD1117S50TR" REG_SOT223-TAB -25.5,-6 r90 bottom
U4 "LD39050PU33R" ICC_DFN6-EPAD_3X3_P095 -34.25,-6.5 r270 bottom
U5 "STLINK-V3EC_Old" ICC_UFBGA201_176+25_10X10_P065 -26.25,-25.5 r270 bottom value=STM32F723IEK6
U6 "74AVC4TD245BQ" ICC_DHVQFN16-EPAD_SOT763-1_2P5X3P5_H0P85_P050 -38.5,-25 r180 bottom
U7 "ESD-TRANSIL" ESD_QFN1610_2N_1K_2A -30,-44.25 r270 top value=ESDA25P35-1U1M
U8 "ECMF02-2AMX6" ESD_QFN-6L_1P7X1P5_P050 -27.75,-40.25 r180 bottom
U9 "74AVC4TD245BQ" ICC_DHVQFN16-EPAD_SOT763-1_2P5X3P5_H0P85_P050 -38.5,-16.5 r180 bottom
U10 "TPS259535DSG" ICC_WSON8-EPAD_2X2_P050 -37.75,-31.5 r180 bottom
U11 "ST730M33R" ICC_SOT23-5L_H1P45 -19.75,-36.5 r270 bottom
U12 "STMPS2151STR" MOS_SOT23-5L -38.5,-38 r0 bottom
U13 "ESDALC6V1W5" ESD_SOT323-5L -43.75,-3.75 r0 bottom
U14 "ESDALC6V1W5" ESD_SOT323-5L -44.75,0.5 r0 bottom
U15 "74AVC4TD245BQ" ICC_DHVQFN16-EPAD_SOT763-1_2P5X3P5_H0P85_P050 -49,-24.25 r90 bottom
U16 "ESD-TRANSIL" ESD_ST0201 -49.75,-45.5 r180 top value=ESDALC6V1-1U2
U17 "ESD-TRANSIL" ESD_ST0201 -39.5,-45.5 r180 top value=ESDALC6V1-1U2
U18 "ESD-TRANSIL" ESD_ST0201 -37.5,-45.65 r180 top value=ESDALC6V1-1U2
U19 "ESD-TRANSIL" ESD_ST0201 -24.25,-49 r270 top value=ESDALC6V1-1U2
X1 "XTAL_4_PINS" CRY_NX2016SA_4P -26.75,-16.75 r0 bottom value=24MHz
? "Comment" PCB_SPECIFICATIONS -181.208,75.148 r0 top

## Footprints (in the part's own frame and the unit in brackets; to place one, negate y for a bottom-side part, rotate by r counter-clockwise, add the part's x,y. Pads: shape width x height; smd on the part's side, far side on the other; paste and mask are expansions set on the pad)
C0402 [mm]
  rect 0.51x0.56 smd mask+0.05: 1(-0.45,0) 2(0.45,0)
  body extent -0.5,-0.3 0.5,0.3, height 0.4
C0603 [mm]
  rect 0.64x0.89 smd mask+0.05: 1(-0.7,0) 2(0.7,0)
  silkscreen extent -0.9,-0.55 1.05,0.55, body extent -0.9,-0.5 0.9,0.5, height 1.4
C0805 [mm]
  rect 0.9x1.4 smd mask+0.05: 1(-0.85,0) 2(0.85,0)
  silkscreen extent -1.3,-0.77 1.3,0.77, body extent -1.1,-0.7 1.1,0.7, height 1.35
C0805_H0P85 [mm] "MCD-01525"
  rect 0.9x1.4 smd mask+0.05: 1(-0.85,0) 2(0.85,0)
  silkscreen extent -1.3,-0.77 1.3,0.77, body extent -1.1,-0.73 1.1,0.72, height 0.95
CON_SAMTEC_CLP-125-02-F-D [mm] "MCD-02705"
  rect 1.8x0.75 smd: 1(-1.5,15.24) 2(1.5,15.24) 3(-1.5,13.97) 4(1.5,13.97) 5(-1.5,12.7) 6(1.5,12.7) 7(-1.5,11.43) 8(1.5,11.43) 9(-1.5,10.16) 10(1.5,10.16) 11(-1.5,8.89) 12(1.5,8.89) 13(-1.5,7.62) 14(1.5,7.62) 15(-1.5,6.35) 16(1.5,6.35) 17(-1.5,5.08) 18(1.5,5.08) 19(-1.5,3.81) 20(1.5,3.81) 21(-1.5,2.54) 22(1.5,2.54) 23(-1.5,1.27) 24(1.5,1.27) 25(-1.5,0) 26(1.5,0) 27(-1.5,-1.27) 28(1.5,-1.27) 29(-1.5,-2.54) 30(1.5,-2.54) 31(-1.5,-3.81) 32(1.5,-3.81) 33(-1.5,-5.08) 34(1.5,-5.08) 35(-1.5,-6.35) 36(1.5,-6.35) 37(-1.5,-7.62) 38(1.5,-7.62) 39(-1.5,-8.89) 40(1.5,-8.89) 41(-1.5,-10.16) 42(1.5,-10.16) 43(-1.5,-11.43) 44(1.5,-11.43) 45(-1.5,-12.7) 46(1.5,-12.7) 47(-1.5,-13.97) 48(1.5,-13.97) 49(-1.5,-15.24) 50(1.5,-15.24)
  silkscreen extent -1.48,-16.09 1.49,16.09, body extent -2.16,-16.09 2.16,16.09, height 2.27
CON_SAMTEC_SSW-106-01-X-S [mm] "MCD-02079"
  rect 1.85x1.85 / inner round 1.85 / far side rect 1.85x1.85 hole 1.1 mask+0.05: 1(-6.35,0)
  round 1.85 hole 1.1 mask+0.05: 2(-3.81,0) 3(-1.27,0) 4(1.27,0) 5(3.81,0) 6(6.35,0)
  silkscreen extent -7.88,-1.2 7.88,1.2, body extent -7.88,-1.21 7.88,1.21, height 8.51
CON_SAMTEC_SSW-108-01-X-S [mm] "MCD-01743"
  rect 1.85x1.85 / inner round 1.85 / far side rect 1.85x1.85 hole 1.1 mask+0.05: 1(-8.89,0)
  round 1.85 hole 1.1 mask+0.05: 2(-6.35,0) 3(-3.81,0) 4(-1.27,0) 5(1.27,0) 6(3.81,0) 7(6.35,0) 8(8.89,0)
  silkscreen extent -10.42,-1.2 10.42,1.2, body extent -10.42,-1.21 10.42,1.21, height 8.51
CON_SAMTEC_SSW-110-01-X-S [mm] "MCD-02080"
  rect 1.85x1.85 / inner round 1.85 / far side rect 1.85x1.85 hole 1.1 mask+0.05: 1(-11.43,0)
  round 1.85 hole 1.1 mask+0.05: 2(-8.89,0) 3(-6.35,0) 4(-3.81,0) 5(-1.27,0) 6(1.27,0) 7(3.81,0) 8(6.35,0) 9(8.89,0) 10(11.43,0)
  silkscreen extent -12.96,-1.2 12.96,1.2, body extent -12.96,-1.21 12.96,1.21, height 8.51
CON_SAMTEC_TMM-105-06-T-D-SM [mm]
  rect 0.89x2.75 smd mask+0.05: 1(-4,-2.375) 2(-4,2.375) 3(-2,-2.375) 4(-2,2.375) 5(0,-2.375) 6(0,2.375) 7(2,-2.375) 8(2,2.375) 9(4,-2.375) 10(4,2.375)
  silkscreen extent -4.99,-2 5,2.02, body extent -5,-3.53 5,3.53, height 7.3
CON_SAMTEC_TSW-102-07-G-S [mm]
  rect 1.85x1.85 / inner round 1.85 / far side rect 1.85x1.85 hole 1 mask+0.05: 1(-1.27,0)
  round 1.85 hole 1 mask+0.05: 2(1.27,0)
  silkscreen extent -2.58,-1.3 2.58,1.3, body extent -2.67,-1.3 2.58,1.3, height 8.38
CON_SAMTEC_TSW-104-07-G-S [mm]
  rect 1.85x1.85 / inner round 1.85 / far side rect 1.85x1.85 hole 1 mask+0.05: 1(-3.81,0)
  round 1.85 hole 1 mask+0.05: 2(-1.27,0) 3(1.27,0) 4(3.81,0)
  silkscreen extent -5.12,-1.3 5.12,1.3, body extent -5.21,-1.37 5.18,1.37, height 8.38
CON_SAMTEC_TSW-119-09-X-D [mm]
  rect 1.85x1.85 / inner round 1.85 / far side rect 1.85x1.85 hole 1 mask+0.05: 1(-22.86,-1.27)
  round 1.85 hole 1 mask+0.05: 2(-22.86,1.27) 3(-20.32,-1.27) 4(-20.32,1.27) 5(-17.78,-1.27) 6(-17.78,1.27) 7(-15.24,-1.27) 8(-15.24,1.27) 9(-12.7,-1.27) 10(-12.7,1.27) 11(-10.16,-1.27) 12(-10.16,1.27) 13(-7.62,-1.27) 14(-7.62,1.27) 15(-5.08,-1.27) 16(-5.08,1.27) 17(-2.54,-1.27) 18(-2.54,1.27) 19(0,-1.27) 20(0,1.27) 21(2.54,-1.27) 22(2.54,1.27) 23(5.08,-1.27) 24(5.08,1.27) 25(7.62,-1.27) 26(7.62,1.27) 27(10.16,-1.27) 28(10.16,1.27) 29(12.7,-1.27) 30(12.7,1.27) 31(15.24,-1.27) 32(15.24,1.27) 33(17.78,-1.27) 34(17.78,1.27) 35(20.32,-1.27) 36(20.32,1.27) 37(22.86,-1.27) 38(22.86,1.27)
  silkscreen extent -24.13,-2.54 24.13,2.54, body extent -24.13,-2.55 24.13,2.54, height 8.38
CON_STDC14_Receiver_MEDIUM_WITH_MIPI10_3D [mm] "compatible with FTSH-105-01-L-DV,-K and FTSH-107-01-L-DV,-K,-A,-P,-ES"
  round 0 hole 1.19 unplated mask+0.05: 0(-5.445,0) 0(5.445,0)
  round 0 hole 0.97 unplated mask+0.05: 0(-3.175,0) 0(3.175,0)
  rect 0.74x2.79 smd mask+0.05: 1(-3.81,-2.032) 2(-3.81,2.032) 3(-2.54,-2.032) 4(-2.54,2.032) 5(-1.27,-2.032) 6(-1.27,2.032) 7(0,-2.032) 8(0,2.032) 9(1.27,-2.032) 10(1.27,2.032) 11(2.54,-2.032) 12(2.54,2.032) 13(3.81,-2.032) 14(3.81,2.032)
  silkscreen extent -6.3,-4.38 6.3,3.6, body extent -6.3,-2.92 6.3,2.92, height 6.6
CON_USB-TYPEC_AMPHENOL_12401826E412A [mm] "MCD-03232"
  round 0 hole 0.65 unplated mask+0.05: 0(-3.6,0)
  round 0 hole 0.65 slot 0.95 at 0 deg unplated mask+0.05: 0(3.6,0)
  rect 0.3x0.7 smd mask+0.05: A1(-2.75,0.66) A2(-2.25,0.66) A3(-1.75,0.66) A4(-1.25,0.66) A5(-0.75,0.66) A6(-0.25,0.66) A7(0.25,0.66) A8(0.75,0.66) A9(1.25,0.66) A10(1.75,0.66) A11(2.25,0.66) A12(2.75,0.66) B1(2.5,-1.04) B2(2,-1.04) B3(1.5,-1.04) B4(1,-1.04) B5(0.5,-1.04) B6(0,-1.04) B7(-0.5,-1.04) B8(-1,-1.04) B9(-1.5,-1.04) B10(-2,-1.04) B11(-2.5,-1.04) B12(-3,-1.04)
  oval 0.8x1.4 hole 0.5 slot 1.1 at 90 deg mask+0.05: SH1(-4.13,-1.25) SH2(4.13,-1.25) SH3(-4.49,-4.7) SH4(4.49,-4.7)
  Top Layer keep-out region: -3.75,-1.95 3.75,-1.95 3.75,-7.24 -3.75,-7.24
  silkscreen extent -4.7,-9.59 4.7,0.91, body extent -4.6,-9.59 4.6,0.91, height 3.25
CPOL_TAJ-B_1210_H210 [mm]
  rect 1.35x2.8 smd mask+0.05: 1(-1.375,0) 2(1.375,0)
  silkscreen extent -2.33,-1.68 1.85,1.68, body extent -1.85,-1.5 1.85,1.5, height 2.11
CRY_NX2016SA_4P [mm]
  rect 0.85x0.75 smd mask+0.05: 1(-0.675,-0.525) 2(0.675,-0.525) 3(0.675,0.525) 4(-0.675,0.525)
  silkscreen extent -1.22,-1.02 1.05,0.85, body extent -1.05,-0.85 1.05,0.85, height 0.7
DIO_SOD523_1A_2K [mm] "MCD-01677"
  rect 0.65x0.3 smd mask+0.05: 1(-0.675,0) 2(0.675,0)
  silkscreen extent -0.65,-0.45 1.05,0.55, body extent -0.85,-0.45 0.85,0.45, height 0.71
ESD_QFN1610_2N_1K_2A [mm] "DFN, 2-Leads, Body 1.60x1.00mm"
  rect 0.55x0.9 smd mask+0.05: 1(-0.625,0) 2(0.625,0)
  silkscreen extent -1.02,-0.58 0.85,0.58, body extent -0.85,-0.55 0.85,0.55, height 0.6
ESD_QFN-6L_1P7X1P5_P050 [mm]
  rect 0.25x0.6 smd mask+0.05: 1(-0.5,-0.65) 2(0,-0.65) 3(0.5,-0.65) 4(0.5,0.65) 5(0,0.65) 6(-0.5,0.65)
  silkscreen extent -0.9,-0.8 0.9,0.8, body extent -0.9,-0.8 0.9,0.8, height 0.56
ESD_SOT323-5L [mm]
  rect 0.4x1.2 smd mask+0.05: 1(-0.65,-0.85) 2(0,-0.85) 3(0.65,-0.85) 4(0.65,0.85) 5(-0.65,0.85)
  silkscreen extent -1.22,-1.21 1.22,0.77, body extent -1.15,-1.05 1.15,1.05, height 1.1
ESD_ST0201 [mm]
  rect 0.425x0.33 smd mask+0.05: 1(-0.312,0) 2(0.312,0)
  silkscreen extent -0.55,-0.3 -0.5,0.3, body extent -0.34,-0.18 0.34,0.18, height 0.34
ICC_DFN6-EPAD_3X3_P095 [mm]
  rect 0.45x0.5 smd mask+0.05: 1(-0.95,-1.3) 2(0,-1.3) 3(0.95,-1.3) 4(0.95,1.3) 5(0,1.3) 6(-0.95,1.3)
  rect 2.5x1.7 smd mask+0.05: EP(0,0)
  silkscreen extent -1.55,-1.55 1.55,1.55, body extent -1.55,-1.55 1.55,1.55, height 1
ICC_DHVQFN16-EPAD_SOT763-1_2P5X3P5_H0P85_P050 [mm] "MCD-01945"
  rect 0.3x0.8 smd mask+0.05: 1(-0.25,1.7) 8(-0.25,-1.7) 9(0.25,-1.7) 16(0.25,1.7)
  rect 0.8x0.3 smd mask+0.05: 2(-1.2,1.25) 3(-1.2,0.75) 4(-1.2,0.25) 5(-1.2,-0.25) 6(-1.2,-0.75) 7(-1.2,-1.25) 10(1.2,-1.25) 11(1.2,-0.75) 12(1.2,-0.25) 13(1.2,0.25) 14(1.2,0.75) 15(1.2,1.25)
  rect 1.2x2.2 smd mask+0.05: 17(0,0)
  silkscreen extent -1.3,-1.8 1.3,1.8, body extent -1.31,-1.81 1.31,1.81, height 1.01
ICC_SOT23-5L_H1P45 [mm]
  rect 0.6x1.3 smd mask+0.05: 1(-0.95,-1.1) 2(0,-1.1) 3(0.95,-1.1) 4(0.95,1.1) 5(-0.95,1.1)
  silkscreen extent -1.75,-1.68 1.6,0.97, body extent -1.52,-1.25 1.52,1.25, height 1.45
ICC_UFBGA201_176+25_10X10_P065 [mm] "IPC"
  round 0.25 smd mask+0.038: A1(-4.55,4.55) A2(-3.9,4.55) A3(-3.25,4.55) A4(-2.6,4.55) A5(-1.95,4.55) A6(-1.3,4.55) A7(-0.65,4.55) A8(0,4.55) A9(0.65,4.55) A10(1.3,4.55) A11(1.95,4.55) A12(2.6,4.55) A13(3.25,4.55) A14(3.9,4.55) A15(4.55,4.55) B1(-4.55,3.9) B2(-3.9,3.9) B3(-3.25,3.9) B4(-2.6,3.9) B5(-1.95,3.9) B6(-1.3,3.9) B7(-0.65,3.9) B8(0,3.9) B9(0.65,3.9) B10(1.3,3.9) B11(1.95,3.9) B12(2.6,3.9) B13(3.25,3.9) B14(3.9,3.9) B15(4.55,3.9) C1(-4.55,3.25) C2(-3.9,3.25) C3(-3.25,3.25) C4(-2.6,3.25) C5(-1.95,3.25) C6(-1.3,3.25) C7(-0.65,3.25) C8(0,3.25) C9(0.65,3.25) C10(1.3,3.25) C11(1.95,3.25) C12(2.6,3.25) C13(3.25,3.25) C14(3.9,3.25) C15(4.55,3.25) D1(-4.55,2.6) D2(-3.9,2.6) D3(-3.25,2.6) D4(-2.6,2.6) D5(-1.95,2.6) D6(-1.3,2.6) D7(-0.65,2.6) D8(0,2.6) D9(0.65,2.6) D10(1.3,2.6) D11(1.95,2.6) D12(2.6,2.6) D13(3.25,2.6) D14(3.9,2.6) D15(4.55,2.6) E1(-4.55,1.95) E2(-3.9,1.95) E3(-3.25,1.95) E4(-2.6,1.95) E12(2.6,1.95) E13(3.25,1.95) E14(3.9,1.95) E15(4.55,1.95) F1(-4.55,1.3) F2(-3.9,1.3) F3(-3.25,1.3) F4(-2.6,1.3) F6(-1.3,1.3) F7(-0.65,1.3) F8(0,1.3) F9(0.65,1.3) F10(1.3,1.3) F12(2.6,1.3) F13(3.25,1.3) F14(3.9,1.3) F15(4.55,1.3) G1(-4.55,0.65) G2(-3.9,0.65) G3(-3.25,0.65) G4(-2.6,0.65) G6(-1.3,0.65) G7(-0.65,0.65) G8(0,0.65) G9(0.65,0.65) G10(1.3,0.65) G12(2.6,0.65) G13(3.25,0.65) G14(3.9,0.65) G15(4.55,0.65) H1(-4.55,0) H2(-3.9,0) H3(-3.25,0) H4(-2.6,0) H6(-1.3,0) H7(-0.65,0) H8(0,0) H9(0.65,0) H10(1.3,0) H12(2.6,0) H13(3.25,0) H14(3.9,0) H15(4.55,0) J1(-4.55,-0.65) J2(-3.9,-0.65) J3(-3.25,-0.65) J4(-2.6,-0.65) J6(-1.3,-0.65) J7(-0.65,-0.65) J8(0,-0.65) J9(0.65,-0.65) J10(1.3,-0.65) J12(2.6,-0.65) J13(3.25,-0.65) J14(3.9,-0.65) J15(4.55,-0.65) K1(-4.55,-1.3) K2(-3.9,-1.3) K3(-3.25,-1.3) K4(-2.6,-1.3) K6(-1.3,-1.3) K7(-0.65,-1.3) K8(0,-1.3) K9(0.65,-1.3) K10(1.3,-1.3) K12(2.6,-1.3) K13(3.25,-1.3) K14(3.9,-1.3) K15(4.55,-1.3) L1(-4.55,-1.95) L2(-3.9,-1.95) L3(-3.25,-1.95) L4(-2.6,-1.95) L12(2.6,-1.95) L13(3.25,-1.95) L14(3.9,-1.95) L15(4.55,-1.95) M1(-4.55,-2.6) M2(-3.9,-2.6) M3(-3.25,-2.6) M4(-2.6,-2.6) M5(-1.95,-2.6) M6(-1.3,-2.6) M7(-0.65,-2.6) M8(0,-2.6) M9(0.65,-2.6) M10(1.3,-2.6) M11(1.95,-2.6) M12(2.6,-2.6) M13(3.25,-2.6) M14(3.9,-2.6) M15(4.55,-2.6) N1(-4.55,-3.25) N2(-3.9,-3.25) N3(-3.25,-3.25) N4(-2.6,-3.25) N5(-1.95,-3.25) N6(-1.3,-3.25) N7(-0.65,-3.25) N8(0,-3.25) N9(0.65,-3.25) N10(1.3,-3.25) N11(1.95,-3.25) N12(2.6,-3.25) N13(3.25,-3.25) N14(3.9,-3.25) N15(4.55,-3.25) P1(-4.55,-3.9) P2(-3.9,-3.9) P3(-3.25,-3.9) P4(-2.6,-3.9) P5(-1.95,-3.9) P6(-1.3,-3.9) P7(-0.65,-3.9) P8(0,-3.9) P9(0.65,-3.9) P10(1.3,-3.9) P11(1.95,-3.9) P12(2.6,-3.9) P13(3.25,-3.9) P14(3.9,-3.9) P15(4.55,-3.9) R1(-4.55,-4.55) R2(-3.9,-4.55) R3(-3.25,-4.55) R4(-2.6,-4.55) R5(-1.95,-4.55) R6(-1.3,-4.55) R7(-0.65,-4.55) R8(0,-4.55) R9(0.65,-4.55) R10(1.3,-4.55) R11(1.95,-4.55) R12(2.6,-4.55) R13(3.25,-4.55) R14(3.9,-4.55) R15(4.55,-4.55)
  silkscreen extent -5.22,-5.07 5.07,5.23, body extent -5.07,-5.07 5.07,5.07, height 0.61
ICC_WSON8-EPAD_2X2_P050 [mm] "MCD-02194"
  rect 0.5x0.3 smd paste+0 mask+0.05: 1(-0.9,0.75) 2(-0.9,0.25) 3(-0.9,-0.25) 4(-0.9,-0.75) 5(0.9,-0.75) 6(0.9,-0.25) 7(0.9,0.25) 8(0.9,0.75)
  rect 0.9x1.6 smd paste+0 mask+0.05: 9(0,0)
  silkscreen extent -0.5,-1 0.5,1, body extent -1,-1 1,1, height 0.81
LED_0603_VISHAY_VLMB1300-GS08_BLUE_1A2K_H0P8 [mm]
  rect 0.8x0.8 smd mask+0.05: 1(-0.75,0) 2(0.75,0)
  silkscreen extent -0.85,-0.53 1.28,0.53, body extent -0.85,-0.45 0.85,0.45, height 0.8
LED_0603_VISHAY_VLMS1300-GS08_RED_1A2K_H0P8 [mm]
  rect 0.8x0.8 smd mask+0.05: 1(-0.75,0) 2(0.75,0)
  silkscreen extent -0.85,-0.53 1.28,0.53, body extent -0.85,-0.45 0.85,0.45, height 0.8
LED_0603_VISHAY_VLMTG1300-GS08_GREEN_1A2K_H0P8 [mm]
  rect 0.8x0.8 smd mask+0.05: 1(-0.75,0) 2(0.75,0)
  silkscreen extent -0.85,-0.53 1.28,0.53, body extent -0.85,-0.45 0.85,0.45, height 0.8
LED_BI-GR_WE-150141SV73110 [mm] "MCD-02631"
  rect 1.1x1.5 smd mask+0.05: 1(-0.75,1.5) 2(0.75,1.5) 3(-0.75,-1.5) 4(0.75,-1.5)
  silkscreen extent -1.65,-1.85 1.5,1.7, body extent -1.5,-1.85 1.5,1.85, height 2.1
MIRE_PLACE_SMD_0P8MM [mm]
  round 0.8 smd paste-10 mask+0.2: 1(0,0)
  Top Layer keep-out circle w0.01: c0,0 r0.804
MOS_SOT23-5L [mm]
  rect 0.6x1.3 smd mask+0.05: 1(-0.95,-1.1) 2(0,-1.1) 3(0.95,-1.1) 4(0.95,1.1) 5(-0.95,1.1)
  silkscreen extent -1.6,-0.95 1.6,0.97, body extent -1.52,-1.25 1.52,1.25, height 1.45
PCB_SPECIFICATIONS [mm]
R0402 [mm]
  rect 0.51x0.7 smd mask+0.05: 1(-0.45,0) 2(0.45,0)
  body extent -0.52,-0.3 0.52,0.3, height 0.4
REG_SOT223-TAB [mm]
  rect 1.5x1.65 smd mask+0.05: 1(-2.3,-3.175) 2(0,-3.175) 3(2.3,-3.175)
  rect 3.5x1.65 smd mask+0.05: 4(0,3.175)
  silkscreen extent -3.35,-2.15 3.35,2.12, body extent -3.35,-3.48 3.35,3.48, height 1.8
Sheetbox_2L2S [mil] "Sheetbox 2 layers / 2 silkscreens"
  round 20 on Mech16: 1(813.78,210.69) 1(2736.9,210.69)
SOLDER-BRIDGE_R0402-0R [mil] "MCD-01619"
  round 10 smd paste-393.7: 1(-17.72,0) 2(20.67,0)
  Top Layer region: 1.48,13.78 8.37,0 1.48,-13.78 30.51,-13.78 30.51,13.78
  Top Layer region: -30.51,-13.78 -30.51,13.78 -8.86,13.78 -2.95,0 -8.86,-13.78
  silkscreen extent -33,-17 33,17, body extent -20,-12 20,12, height 14
STICKER_BOARD_25X5 [mm] "Sticker to mention board reference + serial number"
  silkscreen extent -12.5,-2.5 12.5,2.5, body extent -12.5,-2.5 12.5,2.5, height 0.01
STICKER_PRODUCT_25X5 [mm] "Sticker to mention board CPN code"
  silkscreen extent -12.5,-2.5 12.5,2.5
SWI_C&K_Y78B23110FP__ITT_KMR231GLFS [mm] "MCD-00715"
  rect 0.9x1 smd mask+0.05: 1(2.05,0.8) 2(2.05,-0.8) 3(-2.05,0.8) 4(-2.05,-0.8)
  rect 1.7x0.8 smd mask+0.05: 5(0,1.2)
  silkscreen extent -2.05,-1.43 2.05,1.43, body extent -2.3,-1.5 2.3,1.5, height 2.1
SWI_SPDT-RA_TE-CONNECTIVITY_MLL1200S_1P2T [mm] "MCD-02081"
  rect 1x0.8 smd mask+0.05: 0(-3.75,-1.15) 0(-3.75,1.15) 0(3.75,-1.15) 0(3.75,1.15)
  rect 0.7x1.1 smd mask+0.05: 1(-2.25,2.05) 2(0.75,2.05) 3(2.25,2.05)
  round 0 hole 0.9 unplated mask+0.05: NPTH1(-1.5,0) NPTH2(1.5,0)
  silkscreen extent -3.5,-2.9 3.5,1.4, body extent -3.85,-2.9 3.85,2.24, height 1.75
TP_SMD_1MM [mm]
  round 1 smd paste-10 mask+0.05: 1(0,0)
  silkscreen extent -0.7,-0.7 0.7,0.7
